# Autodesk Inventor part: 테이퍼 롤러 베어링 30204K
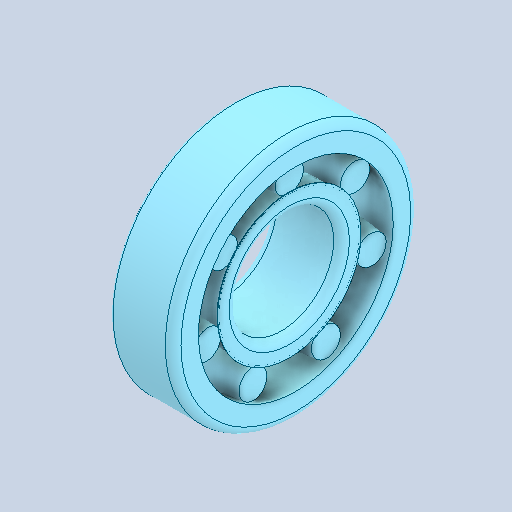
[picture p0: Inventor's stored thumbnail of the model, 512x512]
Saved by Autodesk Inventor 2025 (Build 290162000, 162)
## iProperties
Created: 2026-01
Part Number: 테이퍼 롤러 베어링 30204K
Material: 강철, 연강
Description: 테이퍼 롤러 베어링
Document SubType Name: Modeling
Designer: KDI
Density: 7.85 g/cm^3
Appearance: 기본값
Author: jhkim
Sending System: Autodesk Inventor 2026
Preprocessor: ST-DEVELOPER v20.1
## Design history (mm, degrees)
feature "Solid1"
feature "Solid1:1"
node "솔리드1"
node "솔리드2"
